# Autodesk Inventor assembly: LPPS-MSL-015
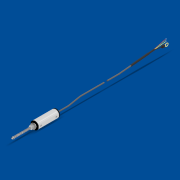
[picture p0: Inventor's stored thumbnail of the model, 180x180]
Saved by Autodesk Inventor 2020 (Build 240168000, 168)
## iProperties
Created: 2019-08
Part Number: LPPS-MSL-015
Document SubType Name: Assembly
Designer: J. Nielson
Author: J. Nielson
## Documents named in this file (5)
- D:\Users\Justin\Documents\CAD Drawings\The Sensor Connection\LPPS\LPPS-MSL\3D\LPPS-MSL-015\LPPS-MSL-015.iam
- D:\Users\Justin\Documents\CAD Drawings\The Sensor Connection\LPPS\LPPS-MSL\3D\LPPS-MSL-015\LPPS-MSL-015 Housing Assembly_SW.ipt
- D:\Users\Justin\Documents\CAD Drawings\The Sensor Connection\LPPS\LPPS-MSL\3D\MSL PARTS\ISO 4035 - M8BS EN.ipt
- D:\Users\Justin\Documents\CAD Drawings\The Sensor Connection\LPPS\LPPS-MSL\3D\LPPS-MSL-015\LPPS-MSL-015 Shaft Assembly_SW.ipt
- D:\Users\Justin\Documents\CAD Drawings\The Sensor Connection\LPPS\LPPS-MSL\3D\LPPS-MSL-015\LPPS-MSL-015 Spring.ipt
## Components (4 placed, 4 different names)
1. LPPS-MSL-015 Housing Assembly_SW:1 — Mate:1, Stroke, Mate:3, Flush:1, Mate:4
2. LPPS-MSL-015 Shaft Assembly_SW:1 — Mate:1, Stroke, Angle:1
3. ISO 4035 - M8BS EN:1 — Mate:3, Angle:2, Mate:4
4. LPPS-MSL-015 Spring:1 — Flush:1
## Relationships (7: Mate 4, Angle 2, Flush 1)
- Mate:1: LPPS-MSL-015 Housing Assembly_SW:1 ↔ LPPS-MSL-015 Shaft Assembly_SW:1
- Stroke [Mate]: LPPS-MSL-015 Housing Assembly_SW:1 ↔ LPPS-MSL-015 Shaft Assembly_SW:1
- Angle:1: LPPS-MSL-015 Shaft Assembly_SW:1
- Mate:3: LPPS-MSL-015 Housing Assembly_SW:1 ↔ ISO 4035 - M8BS EN:1
- Angle:2: ISO 4035 - M8BS EN:1
- Flush:1: LPPS-MSL-015 Housing Assembly_SW:1 ↔ LPPS-MSL-015 Spring:1
- Mate:4: LPPS-MSL-015 Housing Assembly_SW:1 ↔ ISO 4035 - M8BS EN:1
